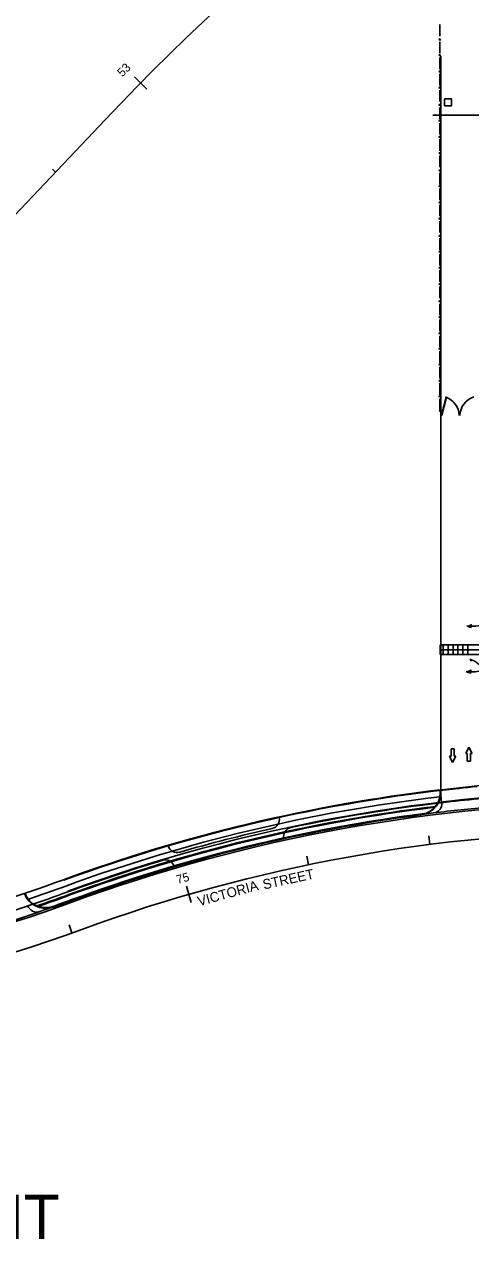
# Model space of a CAD drawing. Extents: x 6711323 to 6714641, y 1869258 to 1871224.
# Drawn here: x 6712223 to 6712585, y 1869258 to 1870245 of the extents above; entities that cross this region are included whole.
import ezdxf

# ---------------------------------------------------------------- set-up
doc = ezdxf.new("R2010")
doc.units = 0
for name, color, linetype in [('AsBuilt Chng(62)', 7, 'Continuous'), ('Contours (7)', 7, 'Continuous'), ('Curb Gutter (21)', 7, 'Continuous'), ('Exist Utils (5)', 7, 'Continuous'), ('Exist Veg_Nat(4)', 7, 'Continuous'), ('Level 10', 7, 'Continuous'), ('Level 11', 7, 'Continuous'), ('Level 13', 7, 'Continuous'), ('Level 14', 7, 'Continuous'), ('Level 16', 7, 'Continuous'), ('Level 2', 7, 'Continuous'), ('Level 21', 7, 'Continuous'), ('Level 3', 7, 'Continuous'), ('Level 32', 7, 'Continuous'), ('Level 35', 7, 'Continuous'), ('Level 46', 7, 'Continuous'), ('Level 60', 7, 'Continuous'), ('Level 63', 7, 'Continuous'), ('Misc CnstDet(22)', 7, 'Continuous'), ('Pave Edges (20)', 7, 'Continuous'), ('Undefined (Lv19)', 7, 'Continuous')]:
    doc.layers.add(name, color=color, linetype=linetype)

msp = doc.modelspace()

# ---------------------------------------------------------------- linework, layer by layer
at = {"layer": 'AsBuilt Chng(62)'}
msp.add_lwpolyline([(6712564.07, 1870178.93), (6712569.77, 1870178.93), (6712569.77, 1870184.44), (6712564.07, 1870184.44)], close=True, dxfattribs=at)
at = {"layer": 'Contours (7)'}
msp.add_line((6712560.56, 1869733.07), (6712560.56, 1869741.07), dxfattribs=at)
at = {"layer": 'Curb Gutter (21)'}
for p, q in [((6712560.97, 1869623.25), (6712560.97, 1870219.06)), ((6713155.55, 1870171.12), (6712554.47, 1870171.12)), ((6712560.97, 1869691.99), (6712560.97, 1869792.69)), ((6712591.64, 1869741.07), (6712560.56, 1869741.07)), ((6712560.97, 1869623.3), (6712560.97, 1869684.64))]:
    msp.add_line(p, q, dxfattribs=at)
at = {"layer": 'Exist Utils (5)'}
msp.add_line((6712560.8, 1870171.12), (6712559.8, 1870171.12), dxfattribs=at)
at = {"layer": 'Exist Veg_Nat(4)'}
for p, q in [((6712583.06, 1869756.33), (6712582.63, 1869755.66)), ((6712583.18, 1869756.33), (6712582.95, 1869756.6)), ((6712583.39, 1869756.28), (6712583.02, 1869755.56)), ((6712583.5, 1869756.28), (6712583.25, 1869756.7)), ((6712583.66, 1869756.28), (6712583.41, 1869755.41)), ((6712583.78, 1869756.28), (6712583.48, 1869756.82)), ((6712584.1, 1869756.25), (6712583.69, 1869756.92)), ((6712583.94, 1869756.28), (6712583.71, 1869755.36)), ((6712584.35, 1869756.23), (6712583.87, 1869756.99)), ((6712584.24, 1869756.23), (6712583.96, 1869755.23)), ((6712584.61, 1869756.23), (6712584.08, 1869757.09)), ((6712584.51, 1869756.23), (6712584.19, 1869755.16)), ((6712584.91, 1869756.2), (6712584.24, 1869757.24)), ((6712584.77, 1869756.2), (6712584.45, 1869755.11)), ((6712585.2, 1869756.18), (6712584.51, 1869757.27)), ((6712585.04, 1869756.18), (6712584.68, 1869755.06)), ((6712585.48, 1869756.18), (6712584.77, 1869757.39)), ((6712585.3, 1869756.2), (6712584.93, 1869755.01)), ((6712585.8, 1869756.18), (6712585.04, 1869757.52)), ((6712585.57, 1869756.18), (6712585.16, 1869754.96)), ((6712586.12, 1869756.18), (6712585.3, 1869757.61)), ((6712585.25, 1869729.26), (6712584.66, 1869729)), ((6712586.12, 1869728.95), (6712584.86, 1869728.63)), ((6712587, 1869728.47), (6712585.15, 1869728.05)), ((6712582.42, 1869719.29), (6712581.98, 1869718.62)), ((6712582.53, 1869719.29), (6712582.3, 1869719.56)), ((6712582.74, 1869719.24), (6712582.37, 1869718.52)), ((6712582.85, 1869719.24), (6712582.6, 1869719.66)), ((6712583.02, 1869719.24), (6712582.76, 1869718.37)), ((6712583.13, 1869719.24), (6712582.83, 1869719.78)), ((6712583.45, 1869719.21), (6712583.04, 1869719.88)), ((6712583.29, 1869719.24), (6712583.06, 1869718.32)), ((6712583.71, 1869719.19), (6712583.22, 1869719.96)), ((6712583.59, 1869719.19), (6712583.32, 1869718.2)), ((6712583.96, 1869719.19), (6712583.43, 1869720.06)), ((6712583.87, 1869719.19), (6712583.55, 1869718.12)), ((6712584.26, 1869719.16), (6712583.59, 1869720.2)), ((6712584.12, 1869719.16), (6712583.8, 1869718.07)), ((6712584.56, 1869719.14), (6712583.87, 1869720.23)), ((6712584.4, 1869719.14), (6712584.03, 1869718.02)), ((6712584.83, 1869719.14), (6712584.12, 1869720.35)), ((6712584.65, 1869719.16), (6712584.28, 1869717.97)), ((6712585.16, 1869719.14), (6712584.4, 1869720.48)), ((6712584.93, 1869719.14), (6712584.51, 1869717.92)), ((6712585.48, 1869719.14), (6712584.65, 1869720.58)), ((6712585.23, 1869719.14), (6712584.74, 1869717.82)), ((6712585.78, 1869719.16), (6712584.93, 1869720.65)), ((6712585.55, 1869719.14), (6712585.04, 1869717.82)), ((6712586.1, 1869719.14), (6712585.2, 1869720.78))]:
    msp.add_line(p, q, dxfattribs=at)
for centre, radius, start, end in [((6712586.68, 1869797.07), 40.9, 263.85918, 283.96709), ((6712578.85, 1869710.61), 19.63, 29.69447, 72.70858), ((6712586.03, 1869760.03), 40.9, 263.85918, 283.96709)]:
    msp.add_arc(centre, radius, start, end, dxfattribs=at)
at = {"layer": 'Level 10'}
for centre, radius, start, end in [((6712716.55, 1868292.52), 1334.32, 96.72554, 110.15752), ((6712716.55, 1868292.52), 1326.98, 96.91209, 110.15752), ((6712716.55, 1868292.52), 1326.32, 96.9418, 110.15752), ((6712716.55, 1868292.52), 1322.3, 97.28774, 110.15752), ((6712716.55, 1868292.52), 1321.63, 97.46257, 110.15752), ((6711821.84, 1870730.35), 1262.51, 288.65737, 290.14932), ((6711821.84, 1870730.35), 1269.84, 288.85864, 290.14932), ((6711821.84, 1870730.35), 1270.51, 288.89027, 290.14932), ((6711821.84, 1870730.35), 1274.53, 289.21984, 290.14932), ((6711821.84, 1870730.35), 1275.2, 289.43952, 290.14932)]:
    msp.add_arc(centre, radius, start, end, dxfattribs=at)
at = {"layer": 'Level 11'}
msp.add_line((6712561.76, 1869612.84), (6712560.69, 1869622.87), dxfattribs=at)
for centre, radius, start, end in [((6712717.46, 1868289.47), 1342.98, 90.36981, 110.14927), ((6712717.45, 1868289.47), 1342.5, 96.06495, 110.14901), ((6712717.46, 1868289.47), 1333, 90.36981, 110.14927), ((6712717.45, 1868289.47), 1342.5, 95.42463, 96.70501), ((6712717.45, 1868289.47), 1323.5, 90.36992, 110.14901), ((6712717.45, 1868289.47), 1332.5, 96.70992, 102.04314), ((6712554.31, 1869611.94), 7.5, 277.03244, 6.06492), ((6712717.45, 1868289.47), 1332.5, 95.41982, 96.70981), ((6712717.45, 1868289.47), 1325, 97.03244, 110.14901), ((6712422.59, 1869599.19), 7.5, 282.68754, 12.36745), ((6712717.45, 1868289.47), 1335, 102.68754, 106.014), ((6712440.99, 1869585.31), 7.5, 102.04314, 192.36745), ((6712347.09, 1869579.87), 7.5, 196.33409, 286.014), ((6712717.45, 1868289.47), 1332.5, 106.6584, 110.14901), ((6712337.62, 1869558.86), 7.5, 16.33409, 106.6584), ((6711821.85, 1870730.35), 1267.5, 288.5952, 290.14901), ((6711821.85, 1870730.35), 1276.5, 273.16115, 290.14901), ((6711821.85, 1870730.35), 1267.5, 286.78697, 288.5952), ((6712233.13, 1869531.43), 7.5, 197.69109, 288.93429), ((6711821.85, 1870730.35), 1275, 288.93429, 290.14901), ((6711821.85, 1870730.35), 1275, 286.44789, 288.93429)]:
    msp.add_arc(centre, radius, start, end, dxfattribs=at)
at = {"layer": 'Level 13'}
msp.add_line((6711851.4, 1869705.32), (6712288.61, 1870167.5), dxfattribs=at)
for centre, radius, start, end in [((6713741.52, 1868793.07), 2000, 102.48979, 136.58998), ((6712717.45, 1868289.47), 1300, 90.36992, 110.14901), ((6711821.85, 1870730.35), 1300, 269.98352, 290.14901)]:
    msp.add_arc(centre, radius, start, end, dxfattribs=at)
at = {"layer": 'Level 14'}
for p, q in [((6712312.44, 1870202.25), (6712317.45, 1870197.35)), ((6712317.45, 1870197.35), (6712322.46, 1870192.46)), ((6712248.42, 1870125.01), (6712245.87, 1870127.41))]:
    msp.add_line(p, q, dxfattribs=at)
for points in [[(6712551.4, 1869585.88), (6712552.29, 1869578.93)], [(6712452.27, 1869569.28), (6712453.69, 1869562.43)], [(6712354.7, 1869545.12), (6712358.58, 1869531.67)], [(6712259.34, 1869513.61), (6712261.71, 1869507.03)]]:
    msp.add_lwpolyline(points, dxfattribs=at)
at = {"layer": 'Level 21'}
for radius, start, end in [(1342.5, 95.42463, 96.70501), (1323.5, 90.36992, 110.14901), (1325, 95.0974, 97.03244)]:
    msp.add_arc((6712717.45, 1868289.47), radius, start, end, dxfattribs=at)
at = {"layer": 'Level 3'}
for centre, radius, start, end in [((6712717.46, 1868289.47), 1343, 96.70901, 110.14921), ((6711821.84, 1870730.35), 1257, 284.61423, 290.14921)]:
    msp.add_arc(centre, radius, start, end, dxfattribs=at)
at = {"layer": 'Level 32'}
for centre, start, end in [((6712542.69, 1869621.06), 278.5833, 7.06861), ((6712240.17, 1869545.07), 199.24106, 287.57699)]:
    msp.add_arc(centre, 18, start, end, dxfattribs=at)
at = {"layer": 'Level 35'}
msp.add_arc((6712240.17, 1869545.07), 17.5, 200.87831, 287.57699, dxfattribs=at)
at = {"layer": 'Level 46'}
for centre, radius, start, end in [((6712716.55, 1868292.52), 1334.32, 96.72554, 110.15752), ((6712543.1, 1869621.08), 18.01, 278.5833, 7.06861), ((6712716.55, 1868292.52), 1326.98, 96.91209, 110.15752), ((6712716.55, 1868292.52), 1326.32, 96.9418, 110.15752), ((6712717.05, 1868291.79), 1327.73, 96.91209, 110.15752), ((6712716.55, 1868292.52), 1322.3, 97.25363, 110.15752), ((6712716.55, 1868292.52), 1321.63, 97.46257, 110.15752), ((6711821.84, 1870730.35), 1262.51, 288.65737, 290.14932), ((6711821.84, 1870730.35), 1269.84, 288.85864, 290.14932), ((6711821.84, 1870730.35), 1270.51, 288.89027, 290.14932), ((6711821.84, 1870730.35), 1274.53, 289.21983, 290.14932), ((6711821.84, 1870730.35), 1275.2, 289.43952, 290.14932)]:
    msp.add_arc(centre, radius, start, end, dxfattribs=at)
at = {"layer": 'Level 60'}
for p, q in [((6712560.18, 1870235.47), (6712560.18, 1870244.82)), ((6712560.91, 1870233.34), (6712559.44, 1870232.11)), ((6712559.49, 1870233.34), (6712560.96, 1870232.11)), ((6712560.18, 1870221.45), (6712560.18, 1870230.8)), ((6712560.91, 1870220.56), (6712559.44, 1870219.33)), ((6712559.49, 1870220.56), (6712560.96, 1870219.33)), ((6712560.18, 1870208.67), (6712560.18, 1870218.02)), ((6712560.91, 1870207.33), (6712559.44, 1870206.1)), ((6712559.49, 1870207.33), (6712560.96, 1870206.1)), ((6712560.18, 1870195.43), (6712560.18, 1870204.78)), ((6712560.91, 1870194.14), (6712559.44, 1870192.91)), ((6712559.49, 1870194.14), (6712560.96, 1870192.91)), ((6712560.18, 1870182.25), (6712560.18, 1870191.6)), ((6712560.91, 1870180.11), (6712559.44, 1870178.89)), ((6712559.49, 1870180.11), (6712560.96, 1870178.89)), ((6712560.18, 1870168.22), (6712560.18, 1870177.57)), ((6712560.91, 1870167.34), (6712559.44, 1870166.11)), ((6712559.49, 1870167.34), (6712560.96, 1870166.11)), ((6712560.18, 1870155.44), (6712560.18, 1870164.79)), ((6712560.91, 1870154.14), (6712559.44, 1870152.91)), ((6712559.49, 1870154.14), (6712560.96, 1870152.91)), ((6712560.18, 1870142.25), (6712560.18, 1870151.6)), ((6712560.91, 1870140.96), (6712559.44, 1870139.73)), ((6712559.49, 1870140.96), (6712560.96, 1870139.73)), ((6712560.18, 1870129.07), (6712560.18, 1870138.42)), ((6712560.91, 1870126.93), (6712559.44, 1870125.7)), ((6712559.49, 1870126.93), (6712560.96, 1870125.7)), ((6712560.18, 1870115.04), (6712560.18, 1870124.39)), ((6712560.91, 1870114.15), (6712559.44, 1870112.92)), ((6712559.49, 1870114.15), (6712560.96, 1870112.92)), ((6712560.18, 1870102.26), (6712560.18, 1870111.61)), ((6712560.91, 1870100.96), (6712559.44, 1870099.73)), ((6712559.49, 1870100.96), (6712560.96, 1870099.73)), ((6712560.18, 1870089.07), (6712560.18, 1870098.42)), ((6712560.91, 1870087.78), (6712559.44, 1870086.55)), ((6712559.49, 1870087.78), (6712560.96, 1870086.55)), ((6712560.18, 1870075.88), (6712560.18, 1870085.23)), ((6712560.91, 1870073.75), (6712559.44, 1870072.52)), ((6712559.49, 1870073.75), (6712560.96, 1870072.52)), ((6712560.18, 1870061.86), (6712560.18, 1870071.21)), ((6712560.91, 1870060.97), (6712559.44, 1870059.74)), ((6712559.49, 1870060.97), (6712560.96, 1870059.74)), ((6712560.18, 1870049.08), (6712560.18, 1870058.43)), ((6712560.91, 1870047.78), (6712559.44, 1870046.56)), ((6712559.49, 1870047.78), (6712560.96, 1870046.56)), ((6712560.18, 1870035.89), (6712560.18, 1870045.24)), ((6712560.91, 1870034.6), (6712559.44, 1870033.37)), ((6712559.49, 1870034.6), (6712560.96, 1870033.37)), ((6712560.18, 1870022.71), (6712560.18, 1870032.06)), ((6712560.91, 1870020.57), (6712559.44, 1870019.35)), ((6712559.49, 1870020.57), (6712560.96, 1870019.35)), ((6712560.18, 1870008.68), (6712560.18, 1870018.03)), ((6712560.91, 1870007.79), (6712559.44, 1870006.57)), ((6712559.49, 1870007.79), (6712560.96, 1870006.57)), ((6712560.18, 1869995.9), (6712560.18, 1870005.25)), ((6712560.91, 1869994.61), (6712559.44, 1869993.38)), ((6712559.49, 1869994.61), (6712560.96, 1869993.38)), ((6712560.18, 1869982.72), (6712560.18, 1869992.07)), ((6712560.91, 1869982.07), (6712559.44, 1869980.84)), ((6712559.49, 1869982.07), (6712560.96, 1869980.84)), ((6712560.18, 1869970.18), (6712560.18, 1869979.53)), ((6712560.91, 1869969.29), (6712559.44, 1869968.06)), ((6712559.49, 1869969.29), (6712560.96, 1869968.06)), ((6712560.18, 1869957.4), (6712560.18, 1869966.75)), ((6712560.91, 1869956.11), (6712559.44, 1869954.88)), ((6712559.49, 1869956.11), (6712560.96, 1869954.88)), ((6712560.18, 1869944.21), (6712560.18, 1869953.56)), ((6712560.91, 1869943.42), (6712559.44, 1869942.19)), ((6712559.49, 1869943.42), (6712560.96, 1869942.19)), ((6712560.18, 1869931.52), (6712560.18, 1869940.87)), ((6712561.19, 1869931.79), (6712559.71, 1869930.56)), ((6712559.76, 1869931.79), (6712561.24, 1869930.56))]:
    msp.add_line(p, q, dxfattribs=at)
at = {"layer": 'Misc CnstDet(22)'}
for p, q in [((6712561.59, 1869927.58), (6712565.49, 1869942.13)), ((6712561.83, 1869927.51), (6712565.73, 1869942.07)), ((6712565.49, 1869942.13), (6712565.73, 1869942.07)), ((6712561.59, 1869927.58), (6712561.83, 1869927.51))]:
    msp.add_line(p, q, dxfattribs=at)
msp.add_lwpolyline([(6712561.04, 1869927.35), (6712561.6, 1869927.35), (6712561.6, 1869928.29), (6712561.04, 1869928.29)], close=True, dxfattribs=at)
for centre, start, end in [((6712559.04, 1869926.37), 3.29974, 70.45263), ((6712593.5, 1869926.37), 109.54737, 176.70026)]:
    msp.add_arc(centre, 17.07, start, end, dxfattribs=at)
at = {"layer": 'Pave Edges (20)'}
for p, q in [((6712939.64, 1869737.07), (6712560.56, 1869737.07)), ((6712562.97, 1869741.07), (6712562.97, 1869733.07)), ((6712570.97, 1869741.07), (6712570.97, 1869733.07)), ((6712578.97, 1869741.07), (6712578.97, 1869733.07))]:
    msp.add_line(p, q, dxfattribs=at)
at = {"layer": 'Undefined (Lv19)'}
for p, q in [((6712608.89, 1869741.07), (6712560.56, 1869741.07)), ((6712566.97, 1869741.07), (6712566.97, 1869733.07)), ((6712566.97, 1869741.07), (6712566.97, 1869733.07)), ((6712574.97, 1869741.07), (6712574.97, 1869733.07)), ((6712574.97, 1869741.07), (6712574.97, 1869733.07)), ((6712582.97, 1869741.07), (6712582.97, 1869733.07)), ((6712582.97, 1869741.07), (6712582.97, 1869733.07)), ((6712674.23, 1869733.07), (6712560.56, 1869733.07)), ((6712608.56, 1869733.07), (6712560.56, 1869733.07)), ((6712571.95, 1869656.67), (6712569.35, 1869656.67)), ((6712569.35, 1869656.67), (6712569.35, 1869650.6)), ((6712571.95, 1869656.67), (6712571.95, 1869650.6)), ((6712583.85, 1869657.86), (6712581.25, 1869652.66)), ((6712583.85, 1869657.86), (6712586.45, 1869652.66)), ((6712569.35, 1869650.6), (6712568.05, 1869650.6)), ((6712570.65, 1869645.39), (6712568.05, 1869650.6)), ((6712570.65, 1869645.39), (6712573.25, 1869650.6)), ((6712573.25, 1869650.6), (6712571.95, 1869650.6)), ((6712581.25, 1869652.66), (6712582.55, 1869652.66)), ((6712582.55, 1869646.59), (6712582.55, 1869652.66)), ((6712582.55, 1869646.59), (6712585.15, 1869646.59)), ((6712585.15, 1869646.59), (6712585.15, 1869652.66)), ((6712585.15, 1869652.66), (6712586.45, 1869652.66))]:
    msp.add_line(p, q, dxfattribs=at)

# ---------------------------------------------------------------- texts
at = {"layer": 'Level 14'}
msp.add_text('75', height=7, rotation=16.11372, dxfattribs=at).set_placement((6712347.61, 1869546.72))
at = {"layer": 'Level 16'}
msp.add_text('53', height=7, rotation=45.20583, dxfattribs=at).set_placement((6712302.68, 1870201.88))
at = {"layer": 'Level 2'}
for s, rotation, p in [('STREET', 12.35913, (6712417.52, 1869542.3)), ('VICTORIA', 15.53261, (6712364.97, 1869528.66))]:
    msp.add_text(s, height=8, rotation=rotation, dxfattribs=at).set_placement(p)
at = {"layer": 'Level 63'}
msp.add_text('CIVIL DATUM POINT', height=36, dxfattribs=at).set_placement((6711786.43, 1869258.43))

doc.saveas('drawing.dxf')
